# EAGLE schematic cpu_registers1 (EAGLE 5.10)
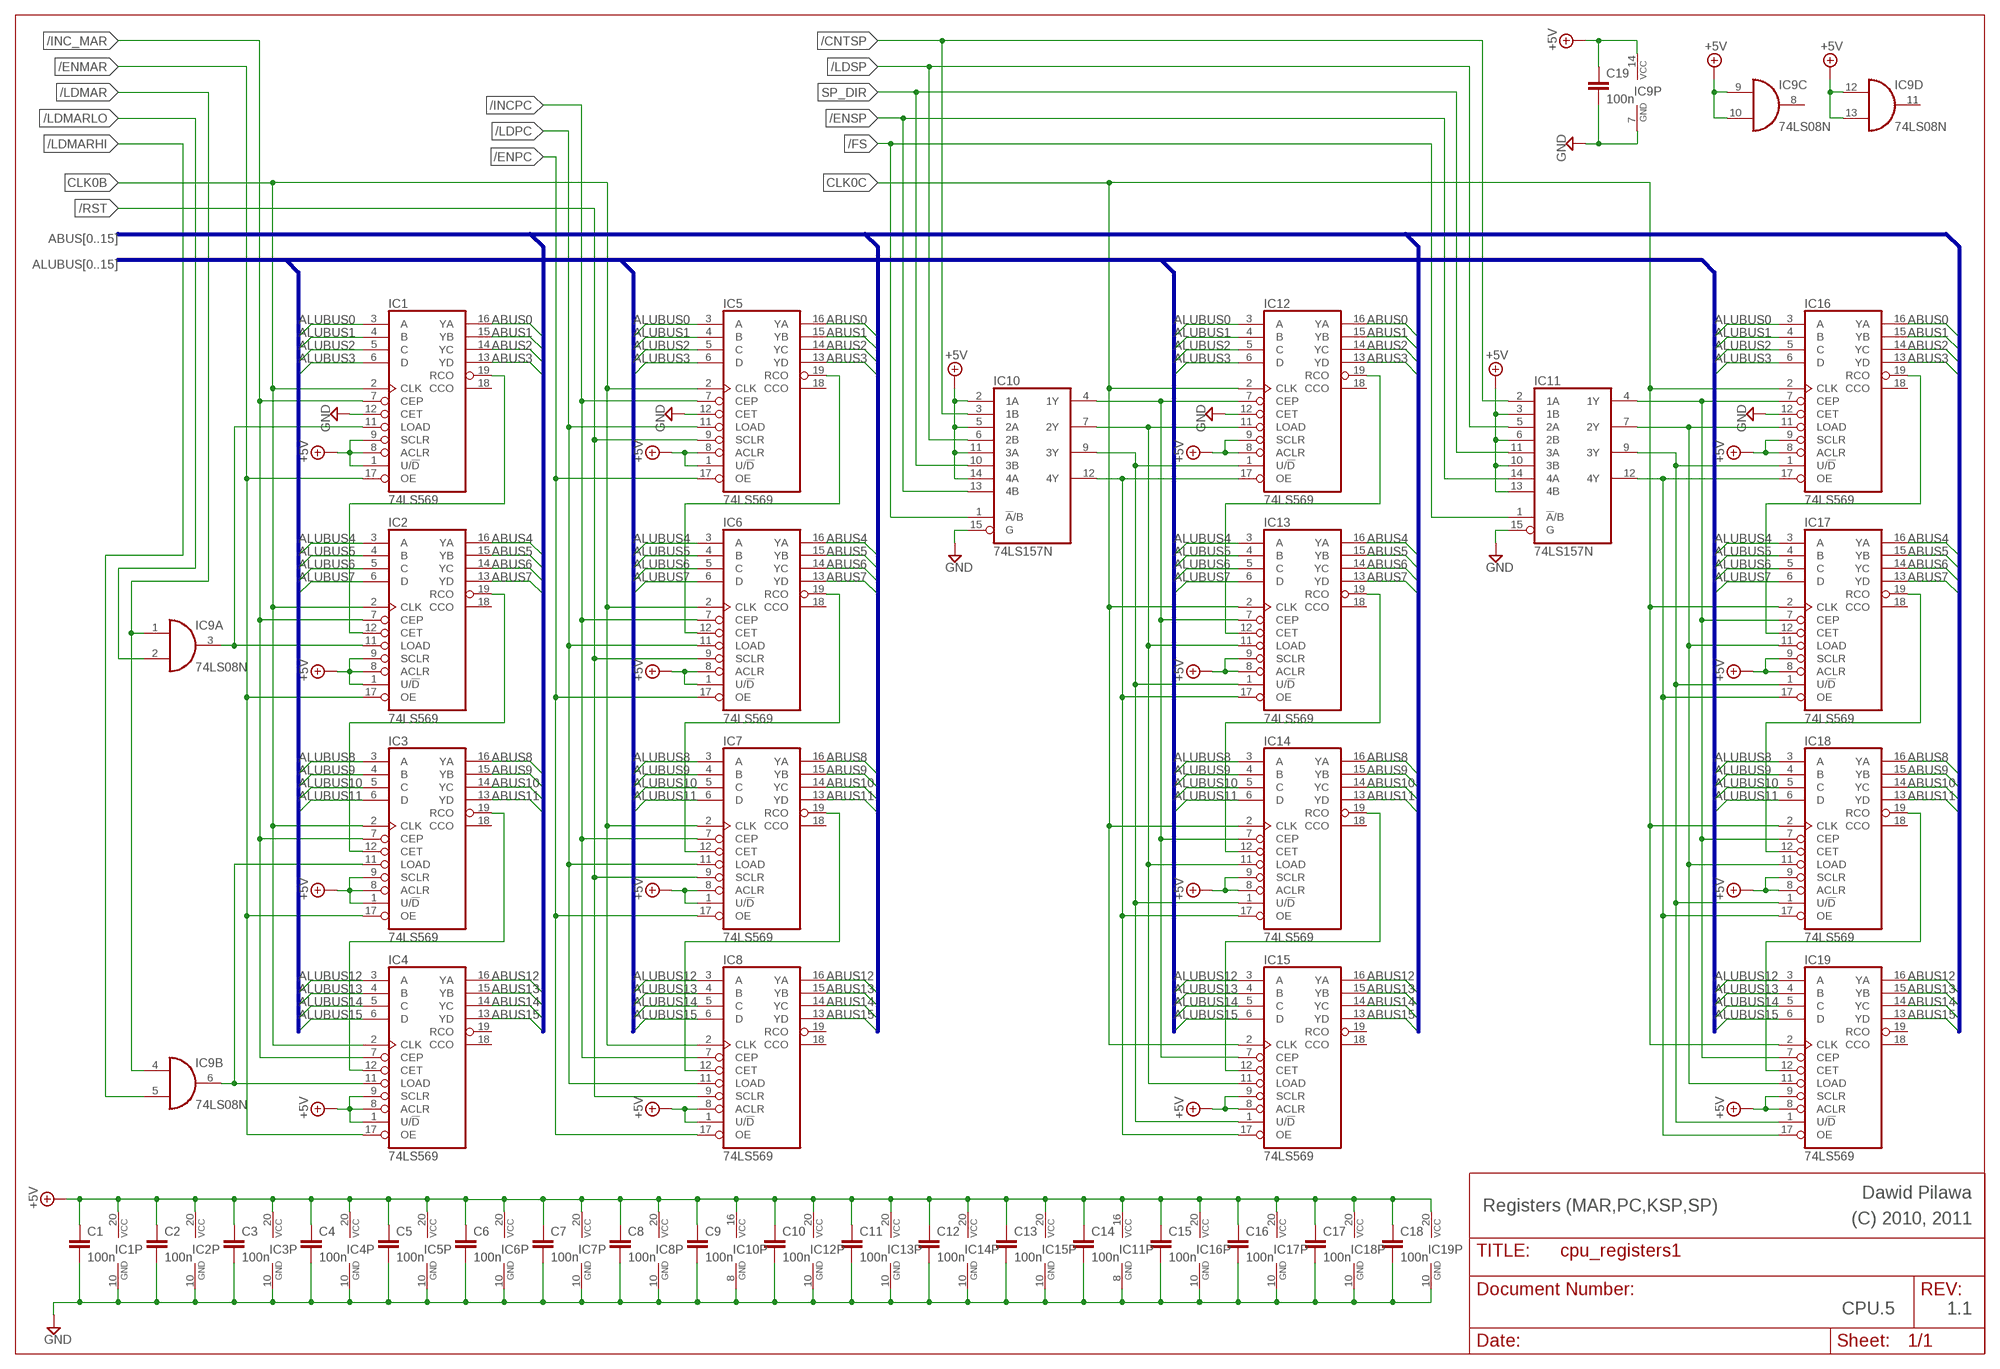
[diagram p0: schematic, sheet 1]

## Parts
C1  100n  C-EU050-024X044  [C050-024X044]
C2  100n  C-EU050-024X044  [C050-024X044]
C3  100n  C-EU050-024X044  [C050-024X044]
C4  100n  C-EU050-024X044  [C050-024X044]
C5  100n  C-EU050-024X044  [C050-024X044]
C6  100n  C-EU050-024X044  [C050-024X044]
C7  100n  C-EU050-024X044  [C050-024X044]
C8  100n  C-EU050-024X044  [C050-024X044]
C9  100n  C-EU050-024X044  [C050-024X044]
C10  100n  C-EU050-024X044  [C050-024X044]
C11  100n  C-EU050-024X044  [C050-024X044]
C12  100n  C-EU050-024X044  [C050-024X044]
C13  100n  C-EU050-024X044  [C050-024X044]
C14  100n  C-EU050-024X044  [C050-024X044]
C15  100n  C-EU050-024X044  [C050-024X044]
C16  100n  C-EU050-024X044  [C050-024X044]
C17  100n  C-EU050-024X044  [C050-024X044]
C18  100n  C-EU050-024X044  [C050-024X044]
C19  100n  C-EU050-024X044  [C050-024X044]
IC1  74LS569  [DIL20]
IC2  74LS569  [DIL20]
IC3  74LS569  [DIL20]
IC4  74LS569  [DIL20]
IC5  74LS569  [DIL20]
IC6  74LS569  [DIL20]
IC7  74LS569  [DIL20]
IC8  74LS569  [DIL20]
IC9  74LS08N  [DIL14]
IC10  74LS157N  [DIL16]
IC11  74LS157N  [DIL16]
IC12  74LS569  [DIL20]
IC13  74LS569  [DIL20]
IC14  74LS569  [DIL20]
IC15  74LS569  [DIL20]
IC16  74LS569  [DIL20]
IC17  74LS569  [DIL20]
IC18  74LS569  [DIL20]
IC19  74LS569  [DIL20]

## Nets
+5V: C1.1 C2.1 C3.1 C4.1 C5.1 C6.1 C7.1 C8.1 C9.1 C10.1 C11.1 C12.1 C13.1 C14.1 C15.1 C16.1 C17.1 C18.1 C19.1 IC1.1(U/!D) IC1.8(ACLR) IC1.9(SCLR) IC1.20(VCC) IC2.1(U/!D) IC2.8(ACLR) IC2.9(SCLR) IC2.20(VCC) IC3.1(U/!D) IC3.8(ACLR) IC3.9(SCLR) IC3.20(VCC) IC4.1(U/!D) IC4.8(ACLR) IC4.9(SCLR) IC4.20(VCC) IC5.1(U/!D) IC5.8(ACLR) IC5.20(VCC) IC6.1(U/!D) IC6.8(ACLR) IC6.20(VCC) IC7.1(U/!D) IC7.8(ACLR) IC7.20(VCC) IC8.1(U/!D) IC8.8(ACLR) IC8.20(VCC) IC9.9(C:I0) IC9.10(C:I1) IC9.12(D:I0) IC9.13(D:I1) IC9.14(P:VCC) IC10.2(1A) IC10.5(2A) IC10.11(3A) IC10.14(4A) IC10.16(VCC) IC11.3(1B) IC11.6(2B) IC11.10(3B) IC11.13(4B) IC11.16(VCC) IC12.8(ACLR) IC12.9(SCLR) IC12.20(VCC) IC13.8(ACLR) IC13.9(SCLR) IC13.20(VCC) IC14.8(ACLR) IC14.9(SCLR) IC14.20(VCC) IC15.8(ACLR) IC15.9(SCLR) IC15.20(VCC) IC16.8(ACLR) IC16.9(SCLR) IC16.20(VCC) IC17.8(ACLR) IC17.9(SCLR) IC17.20(VCC) IC18.8(ACLR) IC18.9(SCLR) IC18.20(VCC) IC19.8(ACLR) IC19.9(SCLR) IC19.20(VCC)
/CNTSP: IC10.3(1B) IC11.2(1A)
/ENMAR: IC1.17(OE) IC2.17(OE) IC3.17(OE) IC4.17(OE)
/ENPC: IC5.17(OE) IC6.17(OE) IC7.17(OE) IC8.17(OE)
/ENSP: IC10.13(4B) IC11.14(4A)
/FS: IC10.1(!A!/B) IC11.1(!A!/B)
/INC_MAR: IC1.7(CEP) IC2.7(CEP) IC3.7(CEP) IC4.7(CEP)
/INCPC: IC5.7(CEP) IC6.7(CEP) IC7.7(CEP) IC8.7(CEP)
/LDMAR: IC9.1(A:I0) IC9.4(B:I0)
/LDMARHI: IC9.5(B:I1)
/LDMARLO: IC9.2(A:I1)
/LDPC: IC5.11(LOAD) IC6.11(LOAD) IC7.11(LOAD) IC8.11(LOAD)
/LDSP: IC10.6(2B) IC11.5(2A)
/RST: IC5.9(SCLR) IC6.9(SCLR) IC7.9(SCLR) IC8.9(SCLR)
ABUS0: IC1.16(YA) IC5.16(YA) IC12.16(YA) IC16.16(YA)
ABUS1: IC1.15(YB) IC5.15(YB) IC12.15(YB) IC16.15(YB)
ABUS2: IC1.14(YC) IC5.14(YC) IC12.14(YC) IC16.14(YC)
ABUS3: IC1.13(YD) IC5.13(YD) IC12.13(YD) IC16.13(YD)
ABUS4: IC2.16(YA) IC6.16(YA) IC13.16(YA) IC17.16(YA)
ABUS5: IC2.15(YB) IC6.15(YB) IC13.15(YB) IC17.15(YB)
ABUS6: IC2.14(YC) IC6.14(YC) IC13.14(YC) IC17.14(YC)
ABUS7: IC2.13(YD) IC6.13(YD) IC13.13(YD) IC17.13(YD)
ABUS8: IC3.16(YA) IC7.16(YA) IC14.16(YA) IC18.16(YA)
ABUS9: IC3.15(YB) IC7.15(YB) IC14.15(YB) IC18.15(YB)
ABUS10: IC3.14(YC) IC7.14(YC) IC14.14(YC) IC18.14(YC)
ABUS11: IC3.13(YD) IC7.13(YD) IC14.13(YD) IC18.13(YD)
ABUS12: IC4.16(YA) IC8.16(YA) IC15.16(YA) IC19.16(YA)
ABUS13: IC4.15(YB) IC8.15(YB) IC15.15(YB) IC19.15(YB)
ABUS14: IC4.14(YC) IC8.14(YC) IC15.14(YC) IC19.14(YC)
ABUS15: IC4.13(YD) IC8.13(YD) IC15.13(YD) IC19.13(YD)
ALUBUS0: IC1.3(A) IC5.3(A) IC12.3(A) IC16.3(A)
ALUBUS1: IC1.4(B) IC5.4(B) IC12.4(B) IC16.4(B)
ALUBUS2: IC1.5(C) IC5.5(C) IC12.5(C) IC16.5(C)
ALUBUS3: IC1.6(D) IC5.6(D) IC12.6(D) IC16.6(D)
ALUBUS4: IC2.3(A) IC6.3(A) IC13.3(A) IC17.3(A)
ALUBUS5: IC2.4(B) IC6.4(B) IC13.4(B) IC17.4(B)
ALUBUS6: IC2.5(C) IC6.5(C) IC13.5(C) IC17.5(C)
ALUBUS7: IC2.6(D) IC6.6(D) IC13.6(D) IC17.6(D)
ALUBUS8: IC3.3(A) IC7.3(A) IC14.3(A) IC18.3(A)
ALUBUS9: IC3.4(B) IC7.4(B) IC14.4(B) IC18.4(B)
ALUBUS10: IC3.5(C) IC7.5(C) IC14.5(C) IC18.5(C)
ALUBUS11: IC3.6(D) IC7.6(D) IC14.6(D) IC18.6(D)
ALUBUS12: IC4.3(A) IC8.3(A) IC15.3(A) IC19.3(A)
ALUBUS13: IC4.4(B) IC8.4(B) IC15.4(B) IC19.4(B)
ALUBUS14: IC4.5(C) IC8.5(C) IC15.5(C) IC19.5(C)
ALUBUS15: IC4.6(D) IC8.6(D) IC15.6(D) IC19.6(D)
CLK0B: IC1.2(CLK) IC2.2(CLK) IC3.2(CLK) IC4.2(CLK) IC5.2(CLK) IC6.2(CLK) IC7.2(CLK) IC8.2(CLK)
CLK0C: IC12.2(CLK) IC13.2(CLK) IC14.2(CLK) IC15.2(CLK) IC16.2(CLK) IC17.2(CLK) IC18.2(CLK) IC19.2(CLK)
GND: C1.2 C2.2 C3.2 C4.2 C5.2 C6.2 C7.2 C8.2 C9.2 C10.2 C11.2 C12.2 C13.2 C14.2 C15.2 C16.2 C17.2 C18.2 C19.2 IC1.10(GND) IC1.12(CET) IC2.10(GND) IC3.10(GND) IC4.10(GND) IC5.10(GND) IC5.12(CET) IC6.10(GND) IC7.10(GND) IC8.10(GND) IC9.7(P:GND) IC10.8(GND) IC10.15(G) IC11.8(GND) IC11.15(G) IC12.10(GND) IC12.12(CET) IC13.10(GND) IC14.10(GND) IC15.10(GND) IC16.10(GND) IC16.12(CET) IC17.10(GND) IC18.10(GND) IC19.10(GND)
N$1: IC1.11(LOAD) IC2.11(LOAD) IC9.3(A:O)
N$2: IC6.19(RCO) IC7.12(CET)
N$3: IC5.19(RCO) IC6.12(CET)
N$4: IC7.19(RCO) IC8.12(CET)
N$5: IC12.19(RCO) IC13.12(CET)
N$6: IC13.19(RCO) IC14.12(CET)
N$7: IC3.11(LOAD) IC4.11(LOAD) IC9.6(B:O)
N$8: IC14.19(RCO) IC15.12(CET)
N$9: IC10.4(1Y) IC12.7(CEP) IC13.7(CEP) IC14.7(CEP) IC15.7(CEP)
N$10: IC1.19(RCO) IC2.12(CET)
N$11: IC2.19(RCO) IC3.12(CET)
N$12: IC3.19(RCO) IC4.12(CET)
N$13: IC10.7(2Y) IC12.11(LOAD) IC13.11(LOAD) IC14.11(LOAD) IC15.11(LOAD)
N$14: IC10.9(3Y) IC12.1(U/!D) IC13.1(U/!D) IC14.1(U/!D) IC15.1(U/!D)
N$15: IC11.9(3Y) IC16.1(U/!D) IC17.1(U/!D) IC18.1(U/!D) IC19.1(U/!D)
N$16: IC10.12(4Y) IC12.17(OE) IC13.17(OE) IC14.17(OE) IC15.17(OE)
N$17: IC11.12(4Y) IC16.17(OE) IC17.17(OE) IC18.17(OE) IC19.17(OE)
N$19: IC16.19(RCO) IC17.12(CET)
N$20: IC17.19(RCO) IC18.12(CET)
N$21: IC18.19(RCO) IC19.12(CET)
N$23: IC11.4(1Y) IC16.7(CEP) IC17.7(CEP) IC18.7(CEP) IC19.7(CEP)
N$24: IC11.7(2Y) IC16.11(LOAD) IC17.11(LOAD) IC18.11(LOAD) IC19.11(LOAD)
SP_DIR: IC10.10(3B) IC11.11(3A)
Unconnected: IC1.18(CCO) IC2.18(CCO) IC3.18(CCO) IC4.18(CCO) IC4.19(RCO) IC5.18(CCO) IC6.18(CCO) IC7.18(CCO) IC8.18(CCO) IC8.19(RCO) IC9.8(C:O) IC9.11(D:O) IC12.18(CCO) IC13.18(CCO) IC14.18(CCO) IC15.18(CCO) IC15.19(RCO) IC16.18(CCO) IC17.18(CCO) IC18.18(CCO) IC19.18(CCO) IC19.19(RCO)

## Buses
ALUBUS[0..15]
ABUS[0..15]

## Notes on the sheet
- Dawid Pilawa
- Registers (MAR,PC,KSP,SP) | (C) 2010, 2011
- CPU.5 | 1.1

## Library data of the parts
C1-C19 = rcl:C-EU: CAPACITOR, European symbol
IC1-IC8 IC12-IC19 = 74xx-eu:74*569: Synchronous binary up/down counter with three-state outputs
IC9 = 74xx-eu:74*08: Quad 2-input AND gate
IC10 IC11 = 74xx-eu:74*157: Quadruple 2-line to 1-line data SELECTOR/MULTIPLEXER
